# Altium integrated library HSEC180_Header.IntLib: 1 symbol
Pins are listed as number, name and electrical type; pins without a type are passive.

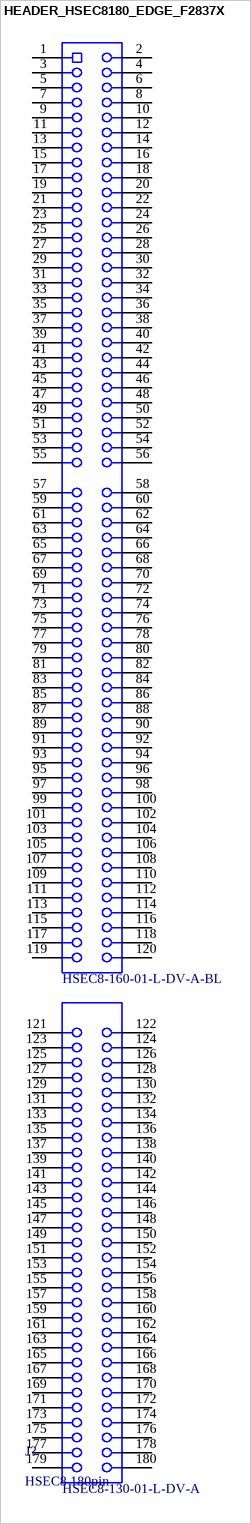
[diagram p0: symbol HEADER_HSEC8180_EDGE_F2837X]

## HEADER_HSEC8180_EDGE_F2837X
designator J?, comment HSEC8 180pin
180 pin (120 + 60) HSEC8 socket, samtec; MANF PART NUMBER: HSEC8-130-01-L-DV-A & HSEC8-160-01-L-DV-A-BL
footprint HEADER_HSEC8_180_DV
pins: 1, 2, 3, 4, 5, 6, 7, 8, 9, 10, 11, 12, 13, 14, 15, 16, 17, 18, 19, 20, 21, 22, 23, 24, 25, 26, 27, 28, 29, 30, 31, 32, 33, 34, 35, 36, 37, 38, 39, 40, 41, 42, 43, 44, 45, 46, 47, 48, 49, 50, 51, 52, 53, 54, 55, 56, 57, 58, 59, 60, 61, 62, 63, 64, 65, 66, 67, 68, 69, 70, 71, 72, 73, 74, 75, 76, 77, 78, 79, 80, 81, 82, 83, 84, 85, 86, 87, 88, 89, 90, 91, 92, 93, 94, 95, 96, 97, 98, 99, 100, 101, 102, 103, 104, 105, 106, 107, 108, 109, 110, 111, 112, 113, 114, 115, 116, 117, 118, 119, 120, 121, 122, 123, 124, 125, 126, 127, 128, 129, 130, 131, 132, 133, 134, 135, 136, 137, 138, 139, 140, 141, 142, 143, 144, 145, 146, 147, 148, 149, 150, 151, 152, 153, 154, 155, 156, 157, 158, 159, 160, 161, 162, 163, 164, 165, 166, 167, 168, 169, 170, 171, 172, 173, 174, 175, 176, 177, 178, 179, 180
